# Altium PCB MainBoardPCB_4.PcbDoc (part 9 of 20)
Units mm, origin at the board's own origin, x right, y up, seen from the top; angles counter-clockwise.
Board outline 333.63 x 349.38 mm, 16 copper layers (L1, L2 (GND), L3 (Sign), L4 (GND), L5 (Sign), L6 (PWR/GND), L7(PWR/GND), L8 (Plane_GND), L9 (PWR/GND), L10 (PWR/GND), L11 (PWR/GND), L12 (Sign), L13 (GND), L14 (Sign), L15 (GND), L16), stack 2.502 mm thick; 2205 components, 1648 nets, 8314 pads, 3172 vias.
Unrouted connection lines stored in the file: 5141.
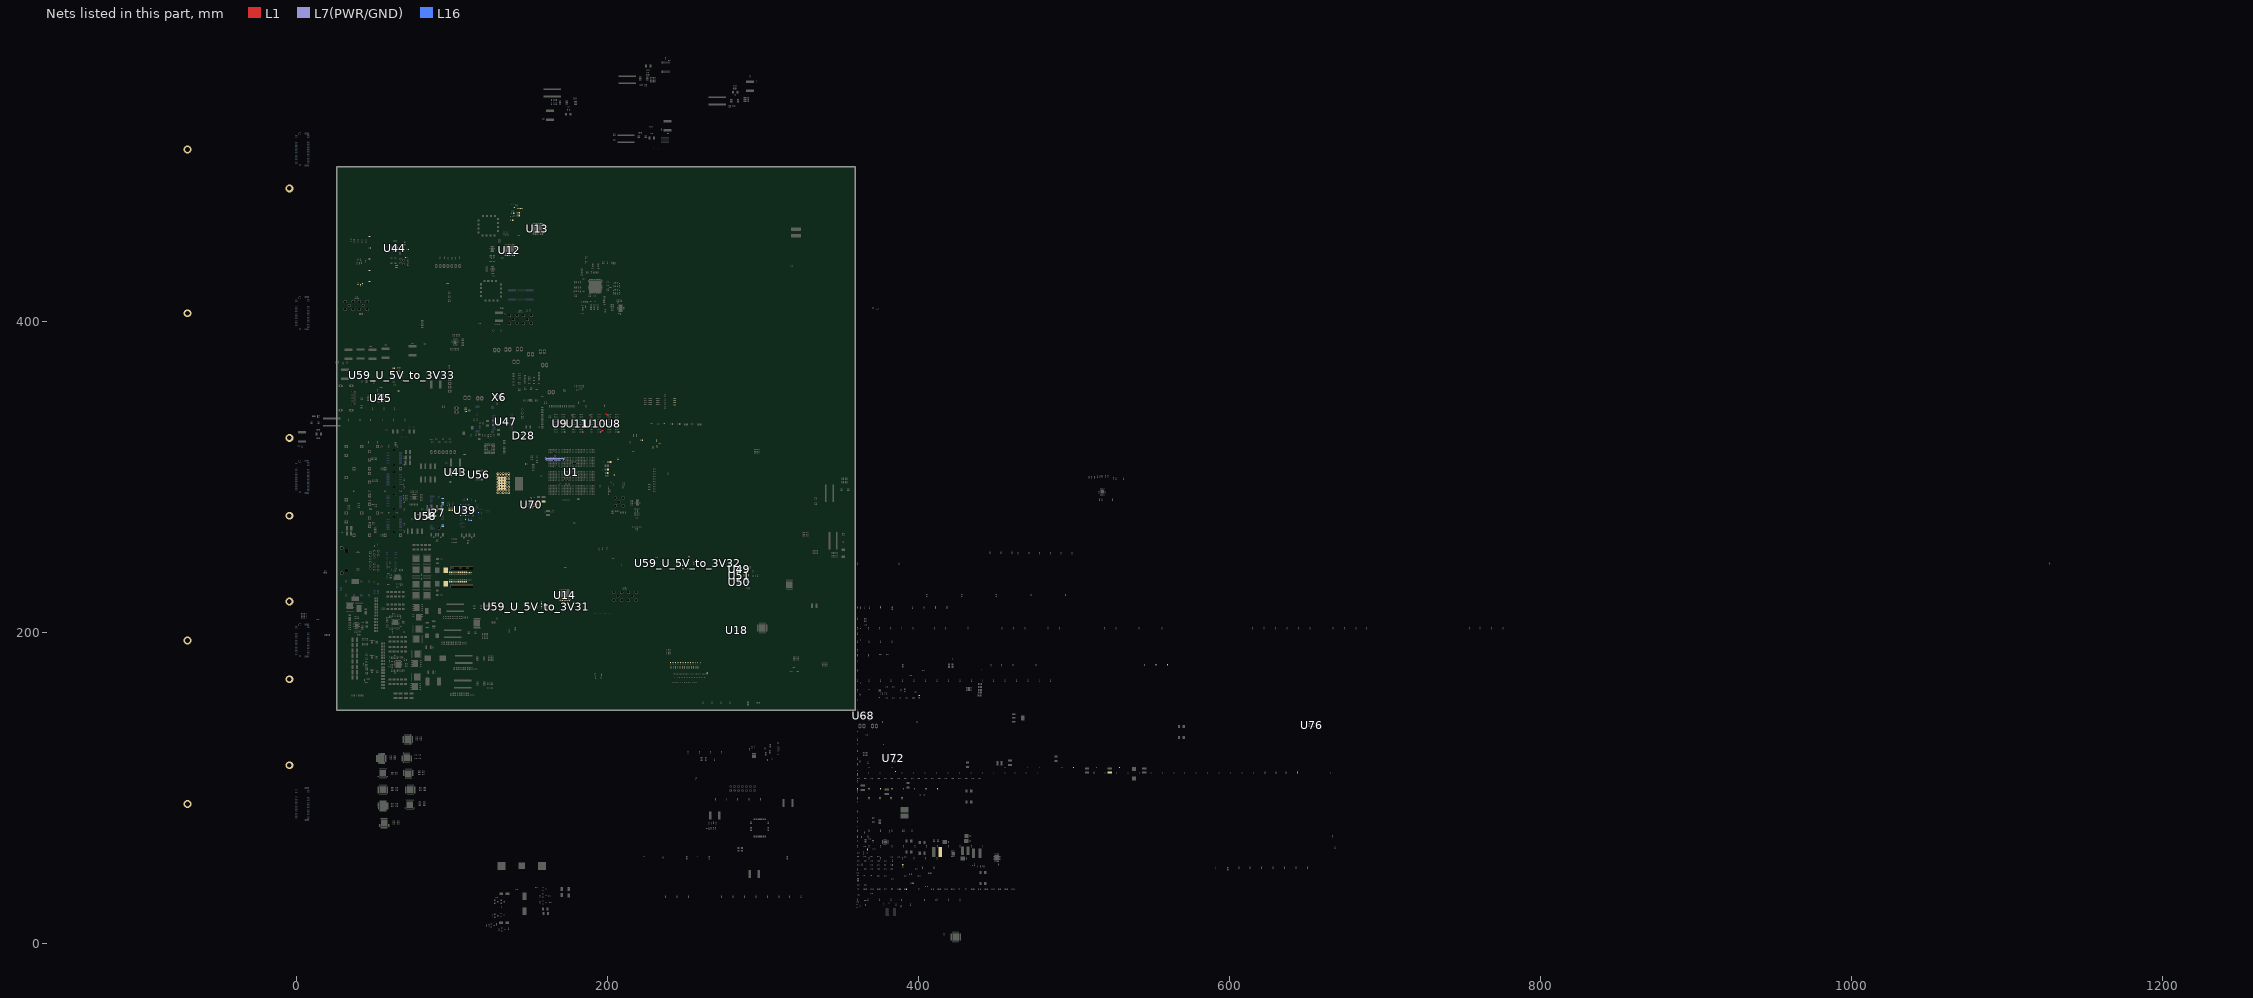
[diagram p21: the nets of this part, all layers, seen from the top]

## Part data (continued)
R532: library part Resistor, "Res Thick Film 0402 75 Ohm 1% 1/10W 100ppm/C Molded SMD SMD Punched Carrier T/R", Case Code (Imperial)=0402, Case Code (Metric)=1005, Manufacturer=Panasonic, Manufacturer Part Number=ERJ-2RKF75R0X, Max Operating Temperature=155°C, Max Power Dissipation=100mW, Min Operating Temperature=-55°C, Package Quantity=1, Supplier Part Number 1=P75.0LDKR-ND, Temperature Coefficient=100ppm/°C, Tolerance=1%, Voltage Rating=50V
R533: library part Resistor, "RES 30 OHM 1% 1/16W 0402", Case/Package=0402, Manufacturer="Stackpole Electronics", Manufacturer Part Number=RMCF0402FT30R0, Max Operating Temperature=155°C, Min Operating Temperature=-55°C, Supplier Part Number 1=RMCF0402FT30R0CT-ND, Temperature Coefficient=100ppm/°C, Tolerance=1%
R536 R537: library part Resistor, "RES SMD 150 OHM 1% 1/10W 0402", Case Code (Imperial)=0402, Case Code (Metric)=1005, Manufacturer=Panasonic, Manufacturer Part Number=ERJ-2RKF1500X, Max Operating Temperature=155°C, Max Power Dissipation=100mW, Min Operating Temperature=-55°C, Package Quantity=1, Supplier Part Number 1=P150LCT-ND, Temperature Coefficient=100ppm/°C, Tolerance=1%, Voltage Rating=50V
R602 R603 R604 R605 R606 R608 R609: library part Resistor, "RES 10K OHM 0.1% 1/16W 0402", Case/Package=0402, Case Code (Metric)=1005, Manufacturer="Stackpole Electronics", Manufacturer Part Number=RNCF0402BTE10K0, Max Operating Temperature=155°C, Max Power Dissipation=63mW, Min Operating Temperature=-55°C, Package Quantity=10000, Supplier Part Number 1=RNCF0402BTE10K0CT-ND, Temperature Coefficient=25ppm/°C, Tolerance=0.1%
R610 R611: library part Resistor, Case/Package=0402, Case Code (Metric)=1005, Manufacturer=Yageo, Manufacturer Part Number=RC0402FR-071K33L, Max Operating Temperature=155°C, Max Power Dissipation=63mW, Min Operating Temperature=-55°C, Package Quantity=1, Power Rating=62.5mW, Supplier Part Number 1=311-1.33KLRCT-ND, Temperature Coefficient=100ppm/°C, Tolerance=1%, Voltage Rating=50V
R612 R614: library part Resistor, Case/Package=0402, Manufacturer="Vishay BCcomponents", Manufacturer Part Number=MCS04020C2203FE000, Max Operating Temperature=125°C, Min Operating Temperature=-55°C, Supplier Part Number 1=749-1566-1-ND, Temperature Coefficient=50ppm/°C, Tolerance=1%
R613 R616: library part Resistor, Case/Package=1206, Case Code (Metric)=3216, Manufacturer="Vishay Dale", Manufacturer Part Number=CRCW12062R40FKEAHP, Max Operating Temperature=155°C, Max Power Dissipation=500mW, Min Operating Temperature=-55°C, Supplier Part Number 1=541-2.40UCT-ND, Temperature Coefficient=100ppm/°C, Tolerance=1%
R617: "RES 0.004 OHM 1% 7W 5931", Case/Package=5931, Manufacturer=Yageo, Max Operating Temperature=170°C, Max Power Dissipation=7W, Min Operating Temperature=-65°C, Resistance=4mR, Supplier Part Number 1=YAG4096CT-ND, Temperature Coefficient=75ppm/°C, Tolerance=1%
R619: library part Resistor, Case/Package=0402, Case Code (Metric)=1005, Manufacturer="Stackpole Electronics", Manufacturer Part Number=RMCF0402FT1K91, Max Operating Temperature=155°C, Max Power Dissipation=63mW, Min Operating Temperature=-55°C, Supplier Part Number 1=RMCF0402FT1K91CT-ND, Temperature Coefficient=100ppm/°C, Tolerance=1%
R620: library part Resistor, Case/Package=0402, Case Code (Metric)=1005, Manufacturer=Yageo, Manufacturer Part Number=RC0402FR-072KL, Max Operating Temperature=155°C, Max Power Dissipation=63mW, Min Operating Temperature=-55°C, Package Quantity=1, Supplier Part Number 1=311-2KLRCT-ND, Temperature Coefficient=100ppm/°C, Tolerance=1%, Voltage Rating=50V
R621: library part Resistor, Case/Package=0402, Case Code (Metric)=1005, Manufacturer="Stackpole Electronics", Manufacturer Part Number=RMCF0402FT147K, Max Operating Temperature=155°C, Max Power Dissipation=63mW, Min Operating Temperature=-55°C, Temperature Coefficient=100ppm/°C, Tolerance=1%
R622: library part Resistor, Case/Package=0402, Case Code (Metric)=1005, Manufacturer="Stackpole Electronics", Manufacturer Part Number=RMCF0402FT340K, Max Operating Temperature=155°C, Max Power Dissipation=63mW, Min Operating Temperature=-55°C, Supplier Part Number 1=RMCF0402FT340KCT-ND, Temperature Coefficient=100ppm/°C, Tolerance=1%
R623: library part Resistor, Case/Package=0402, Case Code (Metric)=1005, Manufacturer=Panasonic, Manufacturer Part Number=ERA-2AEB1431X, Max Operating Temperature=155°C, Max Power Dissipation=63mW, Min Operating Temperature=-55°C, Package Quantity=1, Power Rating=62.5mW, Supplier Part Number 1=P1.43KDCCT-ND, Temperature Coefficient=25ppm/°C, Tolerance=0.1%, Voltage Rating=50V
R624: library part Resistor, Case/Package=0402, Case Code (Metric)=1005, Manufacturer=Panasonic, Manufacturer Part Number=ERJ-2RKF1502X, Max Operating Temperature=155°C, Max Power Dissipation=100mW, Min Operating Temperature=-55°C, Package Quantity=1, Supplier Part Number 1=P15.0KLDKR-ND, Temperature Coefficient=100ppm/°C, Tolerance=1%, Voltage Rating=50V
R625: library part Resistor, "Thick Film Resistors - SMD 1.4K OHM 1%", Case/Package=0402, Case Code (Metric)=1005, Manufacturer=Yageo, Manufacturer Part Number=RC0402FR-071K4L, Max Operating Temperature=155°C, Max Power Dissipation=63mW, Min Operating Temperature=-55°C, Power Rating=62.5mW, Supplier Part Number 1=YAG3039CT-ND, Temperature Coefficient=100ppm/°C, Tolerance=1%, Voltage Rating=50V
R626: library part Resistor, Case/Package=0402, Manufacturer="Vishay BCcomponents", Manufacturer Part Number=MCS04020C2003FE000, Max Operating Temperature=125°C, Min Operating Temperature=-55°C, Supplier Part Number 1=749-1562-1-ND, Temperature Coefficient=50ppm/°C, Tolerance=1%
R627: library part Resistor, Case/Package=0402, Case Code (Metric)=1005, Manufacturer=Yageo, Manufacturer Part Number=RC0402FR-0710K5L, Max Operating Temperature=155°C, Max Power Dissipation=63mW, Min Operating Temperature=-55°C, Power Rating=62.5mW, Supplier Part Number 1=YAG2951CT-ND, Temperature Coefficient=100ppm/°C, Tolerance=1%, Voltage Rating=50V
R628: library part Resistor, Case/Package=0402, Case Code (Metric)=1005, Manufacturer="Stackpole Electronics", Manufacturer Part Number=RMCF0402FT750K, Max Operating Temperature=155°C, Max Power Dissipation=63mW, Min Operating Temperature=-55°C, Supplier Part Number 1=RMCF0402FT750KCT-ND, Temperature Coefficient=100ppm/°C, Tolerance=1%
R631: library part Resistor, Case/Package=0402, Case Code (Metric)=1005, Manufacturer="Stackpole Electronics", Manufacturer Part Number=RMCF0402FT5K90, Max Operating Temperature=155°C, Max Power Dissipation=63mW, Min Operating Temperature=-55°C, Supplier Part Number 1=RMCF0402FT5K90CT-ND, Temperature Coefficient=100ppm/°C, Tolerance=1%
R644: library part Resistor, Case/Package=0402, Case Code (Metric)=1005, Manufacturer=Vishay, Manufacturer Part Number=CRCW04029K10FKED, Max Operating Temperature=155°C, Max Power Dissipation=63mW, Min Operating Temperature=-55°C, Package Quantity=10, Supplier Part Number 1=541-9.10KLCT-ND, Temperature Coefficient=100ppm/°C, Tolerance=1%, Voltage Rating=50V
R645: library part Resistor, Case/Package=0402, Case Code (Metric)=1005, Manufacturer=Panasonic, Manufacturer Part Number=ERA-2AED133X, Max Operating Temperature=155°C, Max Power Dissipation=63mW, Min Operating Temperature=-55°C, Package Quantity=1, Power Rating=62.5mW, Supplier Part Number 1=P13KDECT-ND, Temperature Coefficient=25ppm/°C, Tolerance=0.5%
R647: library part Resistor, "RES SMD 100K OHM 1% 1/16W 0402", Case Code (Imperial)=0402, Case Code (Metric)=1005, Manufacturer=Yageo, Manufacturer Part Number=RC0402FR-07100KL, Max Operating Temperature=155°C, Max Power Dissipation=63mW, Min Operating Temperature=-55°C, Package Quantity=1, Supplier Part Number 1=311-100KLRDKR-ND, Temperature Coefficient=100ppm/°C, Tolerance=1%, Voltage Rating=50V
R648: library part Resistor, "RES SMD 2 OHM 5% 1/16W 0402", Case Code (Imperial)=0402, Case Code (Metric)=1005, Manufacturer=Yageo, Manufacturer Part Number=RC0402JR-072RL, Max Operating Temperature=155°C, Min Operating Temperature=-55°C, Package Quantity=10000, Power Rating=62.5mW, Supplier Part Number 1=311-2.0JRCT-ND, Temperature Coefficient=200ppm/°C, Tolerance=5%, Voltage Rating=50V
R650: library part Resistor, "RES SMD 100M OHM 5% 1/16W 0402", Case Code (Imperial)=0402, Case Code (Metric)=1005, Manufacturer="Stackpole Electronics", Manufacturer Part Number=HMC0402JT100M, Max Operating Temperature=125°C, Max Power Dissipation=63mW, Min Operating Temperature=-55°C, Supplier Part Number 1=HMC0402JT100MCT-ND, Temperature Coefficient=400ppm/°C, Tolerance=5%
R652: library part Resistor, "RES SMD 1M OHM 1% 1/16W 0402", Case Code (Imperial)=0402, Case Code (Metric)=1005, Manufacturer=Yageo, Manufacturer Part Number=RC0402FR-071ML, Max Operating Temperature=155°C, Min Operating Temperature=-55°C, Power Rating=63mW, Supplier Part Number 1=311-1.00MLRDKR-ND, Temperature Coefficient=100ppm/°C, Tolerance=1%, Voltage Rating=50V
R653: library part Resistor, "RES SMD 20 OHM 5% 1/5W 0402", Case Code (Imperial)=0402, Case Code (Metric)=1005, Manufacturer=Rohm, Manufacturer Part Number=ESR01MZPJ200, Max Operating Temperature=155°C, Max Power Dissipation=200mW, Min Operating Temperature=-55°C, Package Quantity=1, Supplier Part Number 1=RHM1011CT-ND, Temperature Coefficient=200ppm/°C, Tolerance=5%
R666: library part Resistor, "RES 0.012 OHM 1% 1/2W 1206", Case/Package=1206, Case Code (Metric)=3216, Manufacturer="Stackpole Electronics", Manufacturer Part Number=CSR1206FK12L0, Max Operating Temperature=155°C, Max Power Dissipation=500mW, Min Operating Temperature=-55°C, Supplier Part Number 1=CSR1206FK12L0CT-ND, Temperature Coefficient=100ppm/°C, Tolerance=1%
R667: library part Resistor, "RES SMD 24.9KOHM 0.1% 1/16W 0402", Case/Package=0402, Case Code (Metric)=1005, Manufacturer=Panasonic, Manufacturer Part Number=ERA-2AEB2492X, Max Operating Temperature=155°C, Max Power Dissipation=63mW, Min Operating Temperature=-55°C, Package Quantity=1, Supplier Part Number 1=P24.9KDCCT-ND, Temperature Coefficient=25ppm/°C, Tolerance=0.1%, Voltage Rating=25V, Voltage Rating (DC)=50V
R668 R676 R745: library part Resistor, "RES SMD 20K OHM 1% 1/16W 0402", Case/Package=0402, Case Code (Metric)=1005, Manufacturer=Vishay, Manufacturer Part Number=CRCW040220K0FKED, Max Operating Temperature=155°C, Max Power Dissipation=63mW, Min Operating Temperature=-55°C, Package Quantity=10, Supplier Part Number 1=51X8496, Temperature Coefficient=100ppm/°C, Tolerance=1%, Voltage Rating=50V
R671 R673: library part Resistor, Case/Package=0402, Case Code (Metric)=1005, Manufacturer=Panasonic, Manufacturer Part Number=ERA-2AEB1871X, Max Operating Temperature=155°C, Max Power Dissipation=63mW, Min Operating Temperature=-55°C, Package Quantity=10000, Power Rating=62.5mW, Supplier Part Number 1=P1.87KDCCT-ND, Temperature Coefficient=25ppm/°C, Tolerance=0.1%
R672: library part Resistor, Case/Package=0402, Case Code (Metric)=1005, Manufacturer=Panasonic, Manufacturer Part Number=ERA-2AEB152X, Max Operating Temperature=155°C, Max Power Dissipation=63mW, Min Operating Temperature=-55°C, Package Quantity=10000, Supplier Part Number 1=P1.5KDCCT-ND, Temperature Coefficient=25ppm/°C, Tolerance=0.1%, Voltage Rating=25V
R674: library part Resistor, Case/Package=0402, Case Code (Metric)=1005, Manufacturer=Panasonic, Manufacturer Part Number=ERA-2AEB153X, Max Operating Temperature=155°C, Max Power Dissipation=63mW, Min Operating Temperature=-55°C, Package Quantity=1, Supplier Part Number 1=P15KDCCT-ND, Temperature Coefficient=25ppm/°C, Tolerance=0.1%, Voltage Rating=25V
R682: library part Resistor, Case/Package=0402, Case Code (Metric)=1005, Manufacturer 1=Yageo, Manufacturer Part Number 1=RC0402FR-077K5L, Max Operating Temperature=155°C, Max Power Dissipation=63mW, Min Operating Temperature=-55°C, Package Quantity=1, Supplier Part Number 1=311-7.50KLRCT-ND, Temperature Coefficient=100ppm/°C, Tolerance=1%, Voltage Rating=50V
R684: library part Resistor, Case/Package=0402, Case Code (Metric)=1005, Manufacturer 1=Yageo, Manufacturer Part Number 1=RC0402FR-077K15L, Max Operating Temperature=155°C, Max Power Dissipation=63mW, Min Operating Temperature=-55°C, Power Rating=62.5mW, Supplier Part Number 1=YAG3235CT-ND, Temperature Coefficient=100ppm/°C, Tolerance=1%, Voltage Rating=50V
R685: library part Resistor, Case/Package=0402, Case Code (Metric)=1005, Manufacturer 1=Yageo, Manufacturer Part Number 1=RC0402FR-075K9L, Max Operating Temperature=155°C, Max Power Dissipation=63mW, Min Operating Temperature=-55°C, Power Rating=62.5mW, Supplier Part Number 1=YAG3197CT-ND, Temperature Coefficient=100ppm/°C, Tolerance=1%, Voltage Rating=50V
R686: library part Resistor, Case/Package=0402, Case Code (Metric)=1005, Manufacturer=Yageo, Manufacturer Part Number=RC0402FR-07412KL, Max Operating Temperature=155°C, Max Power Dissipation=63mW, Min Operating Temperature=-55°C, Power Rating=62.5mW, Supplier Part Number 1=YAG3153CT-ND, Temperature Coefficient=100ppm/°C, Tolerance=1%, Voltage Rating=50V
R687: library part Resistor, Case/Package=0402, Case Code (Metric)=1005, Manufacturer=Panasonic, Manufacturer Part Number=ERA-2AEB5762X, Max Operating Temperature=155°C, Max Power Dissipation=63mW, Min Operating Temperature=-55°C, Package Quantity=1, Power Rating=62.5mW, Supplier Part Number 1=P57.6KDCCT-ND, Temperature Coefficient=25ppm/°C, Tolerance=0.1%, Voltage Rating=50V
R689 R691 R838 R840 R841: library part Resistor, Case/Package=0402, Case Code (Metric)=1005, Manufacturer=Panasonic, Manufacturer Part Number=ERJ-2RKF2002X, Max Operating Temperature=155°C, Max Power Dissipation=100mW, Min Operating Temperature=-55°C, Package Quantity=1, Supplier Part Number 1=P20.0KLCT-ND, Temperature Coefficient=100ppm/°C, Tolerance=1%, Voltage Rating=50V
R695: library part Resistor, Case/Package=0402, Case Code (Metric)=1005, Manufacturer=Panasonic, Manufacturer Part Number=ERA-2AEB101X, Max Operating Temperature=155°C, Max Power Dissipation=63mW, Min Operating Temperature=-55°C, Package Quantity=10000, Supplier Part Number 1=P100DCCT-ND, Temperature Coefficient=25ppm/°C, Tolerance=0.1%, Voltage Rating=25V
R716 R717 R718 R719 R720: library part Resistor, "Thick Film Resistors 0402 261ohms 1% AEC-Q200", Case/Package=0402, Case Code (Metric)=1005, Manufacturer=Panasonic, Manufacturer Part Number=ERJ-2RKF2610X, Max Operating Temperature=155°C, Max Power Dissipation=100mW, Min Operating Temperature=-55°C, Package Quantity=1, Supplier Part Number 1=P261LCT-ND, Temperature Coefficient=100ppm/°C, Tolerance=1%, Voltage Rating=50V
R764: "RES 0.004 OHM 1% 10W 2818", Case/Package=Nonstandard, Manufacturer=Vishay, Max Operating Temperature=170°C, Max Power Dissipation=10W, Min Operating Temperature=-65°C, Resistance=4mR, Supplier Part Number 1=541-3274-1-ND, Temperature Coefficient=200ppm/°C, Tolerance=1%
S1 S5: library part "SW DIP-4"
S2 S3 S4 S6 S7: "WS-TASV SMT Tact Switch 4.5x4.5mm, height 3.8mm, 160gf", Operating Temperature="-40 to +85degC", Rated Current=50mA, Rated Voltage=12VDC
T5 T6 T9 T10 T13 T15 T17 T19: "MOSFET N-CH 30V 53A TDSON-8", Continuous Drain Current (ID)=53A, Drain to Source Breakdown Voltage=30V, Drain to Source Resistance=8mR, Gate to Source Voltage (Vgs)=20V, Input Capacitance=1.7nF, Manufacturer 1=Infineon, Max Operating Temperature=150°C, Max Power Dissipation=35W, Min Operating Temperature=-55°C, Package Quantity=1, Power Dissipation=2.5W, Supplier Part Number 1=BSC080N03LSGATMA1CT-ND, Threshold Voltage=2.2V
T7 T8 T11 T12 T14 T16 T18 T20: "MOSFET, N CH, 100A, 30V, PG-TDSON-8", Case/Package=TO-252-3, Continuous Drain Current (ID)=100A, Drain to Source Breakdown Voltage=30V, Drain to Source Resistance=4.7mR, Gate to Source Voltage (Vgs)=20V, Input Capacitance=4.3nF, Manufacturer 1=Infineon, Max Operating Temperature=150°C, Max Power Dissipation=69W, Min Operating Temperature=-55°C, Package Quantity=5000, Power Dissipation=2.5W, Supplier Part Number 1="BSC030N03LS G-ND", Threshold Voltage=1V
T21: "WE-RJ45 LAN Transformer, THT, 10/100/1000 Base-T, Port 1x1, Tab Up", Operating Temperature="-40 to +85degC"
T22 T23 T27 T30: "MOSFET MOSFT P-Ch -4.3A 50mOhm 10nC Log Lvl", Case/Package=SOT-23, Continuous Drain Current (ID)=4.3A, Current Rating=-4.3A, Drain to Source Breakdown Voltage=-12V, Drain to Source Resistance=50mR, Drain to Source Voltage (Vdss)=12V, Gate to Source Voltage (Vgs)=8V, Input Capacitance=830pF, Manufacturer="International Rectifier", Max Operating Temperature=150°C, Max Power Dissipation=1.3W, Min Operating Temperature=-55°C, Package Quantity=1, Supplier Part Number 1=IRLML6401PBFCT-ND, Threshold Voltage=-550mV
T24 T25 T26 T28 T29 T31 T36: "Trans MOSFET N-CH 8V 6A 3-Pin SOT-23 T/R", Case/Package=SOT-23, Continuous Drain Current (ID)=6A, Drain to Source Voltage (Vdss)=8V, Gate to Source Voltage (Vgs)=5V, Input Capacitance=1.07nF, Manufacturer=Vishay, Max Operating Temperature=150°C, Max Power Dissipation=2.5W, Min Operating Temperature=-55°C, Package Quantity=3000, Power Dissipation=1.3W, Supplier Part Number 1=SI2342DS-T1-GE3CT-ND, Threshold Voltage=800mV
T34: "MOSFET N-CH 60V 25A LFPAK", Continuous Drain Current (ID)=25A, Drain to Source Resistance=14MR, Drain to Source Voltage (Vdss)=60V, Gate to Source Voltage (Vgs)=20V, Input Capacitance=2.03nF, Manufacturer=Renesas, Max Operating Temperature=150°C, Max Power Dissipation=45W, Min Operating Temperature=-55°C, Package Quantity=1, Supplier Part Number 1=968-RJK0651DPB-00#J5
T35: "MOSFET 80V 6.2mOhm@10V 60A N-Ch MV T-FET", Continuous Drain Current (ID)=60A, Drain to Source Breakdown Voltage=80V, Drain to Source Resistance=6.2mR, Gate to Source Voltage (Vgs)=20V, Input Capacitance=2.425nF, Manufacturer=Vishay, Max Operating Temperature=150°C, Max Power Dissipation=69.4W, Min Operating Temperature=-55°C, On-State Resistance=9.5MR, Package Quantity=1, Supplier Part Number 1=SIJ482DP-T1-GE3CT-ND, Threshold Voltage=1.5V
TP1_I2C_Bridge TP1_I2C_Bridge_2 TP1_I2C_Bridge_3 TP2_I2C_Bridge TP2_I2C_Bridge_2 TP2_I2C_Bridge_3 TP3_I2C_Bridge TP3_I2C_Bridge_2 TP3_I2C_Bridge_3 TP4_I2C_Bridge TP4_I2C_Bridge_2 TP4_I2C_Bridge_3 TP5_I2C_Bridge TP5_I2C_Bridge_2 TP5_I2C_Bridge_3 TP6_I2C_Bridge TP6_I2C_Bridge_2 TP6_I2C_Bridge_3 TP7_I2C_Bridge_2 TP8_I2C_Bridge TP8_I2C_Bridge_2 TP8_I2C_Bridge_3 TP9_I2C_Bridge TP9_I2C_Bridge_2 TP9_I2C_Bridge_3 TP10_I2C_Bridge TP10_I2C_Bridge_2 TP10_I2C_Bridge_3 TP11_I2C_Bridge TP11_I2C_Bridge_2 TP11_I2C_Bridge_3 TP12_I2C_Bridge_2 TP13_I2C_Bridge_2 TP14_I2C_Bridge_2 TP15_I2C_Bridge TP15_I2C_Bridge_2 TP15_I2C_Bridge_3 TP16_I2C_Bridge TP16_I2C_Bridge_2 TP16_I2C_Bridge_3 TP17_I2C_Bridge TP17_I2C_Bridge_2 TP17_I2C_Bridge_3 TP18_I2C_Bridge TP18_I2C_Bridge_2 TP18_I2C_Bridge_3 TP19 TP20 TP33 TP34 TP35 TP36 TP37 TP38 TP39 TP40 TP41 TP42 TP43 TP44 TP45 TP46 TP47 TP48 TP49 TP50_SPI_bridge2 TP50_SPI_bridge3 TP51_SPI_bridge2 TP51_SPI_bridge3 TP52_SPI_bridge2 TP52_SPI_bridge3 TP53_SPI_bridge1 TP53_SPI_bridge2 TP53_SPI_bridge3 TP54_SPI_bridge2 TP55_SPI_bridge2 TP56_SPI_bridge1 TP56_SPI_bridge2 TP56_SPI_bridge3 TP57_SPI_bridge1 TP57_SPI_bridge2 TP57_SPI_bridge3 TP58_SPI_bridge1 TP58_SPI_bridge2 TP58_SPI_bridge3 TP59_SPI_bridge1 TP59_SPI_bridge2 TP59_SPI_bridge3 TP60_U_Translator_I2C1 TP60_U_Translator_I2C2 TP60_U_Translator_I2C3 TP60_U_Translator_I2C4 TP61_U_Translator_I2C1 TP61_U_Translator_I2C2 TP61_U_Translator_I2C3 TP61_U_Translator_I2C4 TP62 TP63 TP64 TP65 TP66 TP67 TP68 TP69 TP70 TP71 TP72 TP73 TP74 TP75 TP76 TP77 TP78 TP79 TP80 TP81 TP82 TP83 TP84 TP85 TP86 TP87 TP88 TP91 TP92: "TEstPoint", Color=Black, Flammability Rating="UL94 V-0", Manufacturer="Keystone Electronics", Manufacturer Part Number=5001, Package Quantity=100, Supplier Part Number 1=36-5001-ND
U1: "FPGA Zynq UltraScale+ Family 192150 Cells 20nm Technology 0.85V 900-Pin FCBGA Tray", Case/Package=FCBGA, Frequency=500MHz, Manufacturer=Xilinx, Manufacturer Part Number=XCZU4CG-1FBVB900E, Max Operating Temperature=100°C, Min Operating Temperature=0°C, Supplier Part Number 1=217-CZU4CG-1FBVB900E
U3_I2C_Bridge U3_I2C_Bridge_2 U3_I2C_Bridge_3: "8X I2C Switch", Case/Package=VQFN, Manufacturer="Texas Instruments", Manufacturer Part Number=TCA9548ARGER, Max Operating Temperature=85°C, Max Supply Current=80uA, Max Supply Voltage=5.5V, Min Operating Temperature=-40°C, Min Supply Voltage=1.65V, On-State Resistance=70R, Package Quantity=3000, Supplier Part Number 1=296-39222-1-ND
U4 U5 U48: Manufacturer 1="Texas Instruments", Supplier Part Number 1=296-53412-1-ND
U6 U7 U17 U18 U20 U21 U22 U23 U46: "Current Limit Load Switch with OVP and TRCB, 28 V, 5 A", Manufacturer 1="ON Semiconductor", Supplier Part Number 1=863-FPF2895CUCX
U8 U9 U10 U11: "RAM 8GB", Frequency=1.2GHz, Manufacturer="Micron Technology", Manufacturer Part Number=MT40A512M16JY-083EIT:BTR, Max Operating Temperature=95°C, Min Operating Temperature=-40°C, Supplier Part Number 1=557-1690-2-ND
U12 U13 U14: "Dystrybutor Zegarów", Manufacturer="Analog Devices", Manufacturer Part Number=LTC6952IUKG#PBF, Supplier Part Number 1=LTC6952IUKG#PBF-ND
U15 U24_SPI_bridge1 U24_SPI_bridge2 U24_SPI_bridge3 U25_SPI_bridge1 U25_SPI_bridge2 U25_SPI_bridge3 U26_SPI_bridge1 U26_SPI_bridge2 U26_SPI_bridge3 U27_SPI_bridge1 U27_SPI_bridge2 U27_SPI_bridge3 U28_SPI_bridge1 U28_SPI_bridge2 U28_SPI_bridge3 U43 U53 U56 U57 U79: Manufacturer 1="Texas Instruments", Supplier Part Number 1=296-SN74AXC4T774PWRCT-ND
U16: Manufacturer="Texas Instruments", Manufacturer Part Number=LMK05028RGCR, Supplier Part Number 1=296-49099-1-ND
U19: "Quad 40 V / 1 A Step-Down Switching Regulator with 100% Duty Cycle Operation, 28-pin QFN (UFD-28), -40 to 125 degC, Pb-Free", Manufacturer="Linear Technology", Supplier Part Number 1=LT3504EUFD#PBF-ND
U30: "DAC 20bit", Case/Package=SSOP, Manufacturer="Texas Instruments", Manufacturer Part Number=DAC1220E, Max Operating Temperature=85°C, Max Supply Voltage=5.25V, Min Operating Temperature=-40°C, Min Supply Voltage=4.75V, Nominal Supply Current=460uA, Operating Supply Voltage=5V, Package Quantity=75, Power Consumption=2.5mW, Supplier Part Number 1=DAC1220E-ND
U31 U32: "IC BUFFER 2:4 LVPECL MUX 16QFN", Case/Package=QFN, Frequency=1.25GHz, Manufacturer 1="Silicon Labs", Max Operating Temperature=85°C, Max Supply Voltage=3.63V, Min Operating Temperature=-40°C, Min Supply Voltage=2.38V, Nominal Supply Current=210mA, Package Quantity=100, Supplier Part Number 1=336-2500-5-ND
U33: "IC, BUF LVPECL CLOCK DRVR 16-VQFN", Case/Package=QFN, Frequency=800MHz, Input Current=10uA, Manufacturer="Texas Instruments", Max Operating Temperature=85°C, Max Supply Voltage=3.6V, Min Operating Temperature=-40°C, Min Supply Voltage=3V, Package Quantity=1, Supplier Part Number 1=296-17045-1-ND
U34 U37 U38: "Analog Devices", Case/Package="LFCSP EP", Max Input Voltage=20V, Max Operating Temperature=85°C, Max Output Current=30A, Min Input Voltage=2.75V, Min Operating Temperature=-40°C, Nominal Supply Current=4.5mA, Operating Supply Current=100uA, Output Current=25A, Output Voltage=18V, Supplier Part Number 1=ADP1850ACPZ-R7CT-ND, Switching Frequency=1.5MHz
U35_I2C_Expander1 U35_I2C_Expander1_1 U35_I2C_Expander2 U35_I2C_Expander2_1 U35_I2C_Expander3 U35_I2C_Expander3_1 U35_I2C_Expander? U35_I2C_Expander_10 U35_I2C_Expander_11 U35_I2C_Expander_12 U35_I2C_Expander_13 U35_I2C_Expander_14 U35_I2C_Expander_16 U35_I2C_Expander_16_1: "16-Bit I/O Expander with Serial Interface, 28-Pin QFN, Extended Temperature", Manufacturer=Microchip, Supplier Part Number 1=MCP23017-E/ML-ND
U36_U_Translator_I2C1 U36_U_Translator_I2C2 U36_U_Translator_I2C3 U36_U_Translator_I2C4: "I2C [V] Level translator", Low Level Output Current=128mA, Manufacturer="Texas Instruments", Manufacturer Part Number=PCA9306DQER, Max Operating Temperature=85°C, Max Supply Voltage=5V, Min Operating Temperature=-40°C, Min Supply Voltage=0uV, Package Quantity=1, Supplier Part Number 1=296-27957-1-ND
U39: "IC ETHERNET PHY 48VQFN", Case/Package=VQFN, Manufacturer 1="Texas Instruments", Max Operating Temperature=105°C, Max Supply Voltage=2.625V, Min Operating Temperature=-40°C, Min Supply Voltage=950mV, Supplier Part Number 1=296-43254-1-ND
U40 U42 U49 U50 U51 U59_5V_to_3V3_for_FTDI U59_U_5V_to_3V31 U59_U_5V_to_3V32 U59_U_5V_to_3V33: "IC REG LDO ADJ 1.5A 8DFN", Case/Package=DFN, Dropout Voltage=330mV, Input Bias Current=120uA, Manufacturer 1=Microchip, Max Input Voltage=6V, Max Operating Temperature=125°C, Max Output Current=1.5A, Min Input Voltage=2.3V, Min Operating Temperature=-40°C, Output Voltage=5V, Package Quantity=3300, Reference Voltage=410mV, Supplier Part Number 1=MCP1727T-ADJE/MFCT-ND
U41: "IC FLASH 64G MMC", Manufacturer 1="Micron Technology", Supplier Part Number 1=340-296563-REEL
U44: "IC SUPERVISORY CIRC DL 16TQFN", Manufacturer=Maxim, Max Operating Temperature=125°C, Max Power Dissipation=2W, Max Supply Voltage=28V, Min Operating Temperature=-40°C, Min Supply Voltage=2.2V, Number of Voltages Monitored=2, Operating Supply Current=52uA, Package Quantity=2500, Supplier Part Number 1=MAX16025TE+TCT-ND
U45: "IC TXRX USB 2.0 FLEXPWR 32QFN", Case/Package=QFN, Frequency=60MHz, Manufacturer 1=Microchip, Max Operating Temperature=85°C, Min Operating Temperature=-40°C, Operating Supply Current=18uA, Operating Supply Voltage=5.5V, Package Quantity=4000, Supplier Part Number 1=USB3320C-EZK-DKR-ND
U47: "Memory Card Interface 25-WLCSP (2.04x2.04)", Manufacturer 1="Nexperia USA", Supplier Part Number 1=1727-8607-1-ND
U54: "MICROCHIP - 93LC56BT-I/OT. - 2K, 128 X 16, SERIAL EE, IND ROHS COMPLIANT: YES", Case/Package=SOT-23, Frequency=2MHz, Manufacturer=Microchip, Max Operating Temperature=85°C, Max Supply Voltage=5.5V, Min Operating Temperature=-40°C, Min Supply Voltage=2.5V, Nominal Supply Current=2mA, Package Quantity=3000, Supplier Part Number 1=93LC56BT-I/OTCT-ND
U55: "IC USB HS QUAD UART/SYNC 64-LQFP", Case/Package=LQFP, Dual Supply Voltage=3.3V, Manufacturer 1=FTDI, Max Operating Temperature=85°C, Max Supply Voltage=3.63V, Min Operating Temperature=-40°C, Min Supply Voltage=1.62V, Operating Supply Current=70mA, Package Quantity=1000, Supplier Part Number 1=768-1026-1-ND
U58: Manufacturer 1=STMicroelectronics, Supplier Part Number 1=497-19784-1-ND
U60 U69: "IC REG LIN POS ADJ 2A 16LFCSP", Case/Package="LFCSP EP", Dropout Voltage=160mV, Manufacturer="Analog Devices", Max Input Voltage=3.6V, Max Operating Temperature=125°C, Max Output Current=2A, Max Output Voltage=3V, Max Supply Current=1.8mA, Min Current Limit=2.4A, Min Input Voltage=1.6V, Min Operating Temperature=-40°C, Min Output Voltage=750mV, Output Voltage Accuracy=1%, Power Supply Rejection Ratio (PSRR)=70dB, Supplier Part Number 1=ADP1741ACPZ-R7CT-ND
U61 U70: "IC REG LINEAR POS ADJ 1A 20QFN", Case/Package=QFN, Dropout Voltage=130mV, Manufacturer="Texas Instruments", Max Operating Temperature=125°C, Min Current Limit=1.5A, Min Operating Temperature=-40°C, Output Current=1A, Output Voltage=5V, Quiescent Current=2mA, Supplier Part Number 1=296-43312-1-ND
U62: "LINEAR TECHNOLOGY         LT3042EDD#PBF             LDO Voltage Regulator, Adjustable, 1.8V to 20V in, 350mV drop, 0V to 15V/0.2A out, DFN-10", Case/Package=DFN, Dropout Voltage=350mV, Manufacturer="Analog Devices / Linear Technology", Max Input Voltage=20V, Max Operating Temperature=125°C, Max Output Voltage=15V, Min Current Limit=220mA, Min Input Voltage=1.8V, Min Operating Temperature=-40°C, Min Output Voltage=0uV, Output Current=200mA, Supplier Part Number 1=LT3042EDD#PBF-ND
U63: "IC TXRX CAN 1MBPS SOT23-8", Case/Package=SOT-23-8, Manufacturer=Maxim, Max Operating Temperature=85°C, Max Supply Current=70mA, Max Supply Voltage=3.465V, Min Operating Temperature=-40°C, Min Supply Voltage=3.135V, Operating Supply Current=35mA, Operating Supply Voltage=3.3V, Package Quantity=1, Supplier Part Number 1=MAX3051EKA+TCT-ND
U64_U_Pomiar_pradu_napiecia_1 U64_U_Pomiar_pradu_napiecia_2 U64_U_Pomiar_pradu_napiecia_3 U64_U_Pomiar_pradu_napiecia_4 U64_U_Pomiar_pradu_napiecia_5 U64_U_Pomiar_pradu_napiecia_6 U64_U_Pomiar_pradu_napiecia_7 U64_U_Pomiar_pradu_napiecia_8 U64_U_Pomiar_pradu_napiecia_9 U64_U_Pomiar_pradu_napiecia_10 U64_U_Pomiar_pradu_napiecia_11 U72: "IC MONITOR PWR/CURR BIDIR 10MSOP", Case/Package=VSSOP, Input Bias Current=10uA, Input Offset Voltage (Vos)=2.5uV, Manufacturer="Texas Instruments", Max Operating Temperature=125°C, Max Supply Voltage=5.5V, Min Operating Temperature=-40°C, Min Supply Voltage=2.7V, Nominal Supply Current=330uA, Output Current=10mA, Package Quantity=1, Supplier Part Number 1=296-29034-1-ND
U65: "IC REG CTRLR BUCK 20-TQFN", Manufacturer=Maxim, Supplier Part Number 1=MAX17557ATP+-ND
U67 U68: "IC PWR SUPPLY SEQUENCER SOT23-6", Case/Package=SOT-23-6, Manufacturer="TI National Semiconductor", Max Operating Temperature=125°C, Max Supply Voltage=5.5V, Min Operating Temperature=-40°C, Min Supply Voltage=2.7V, Number of Voltages Monitored=3, Operating Supply Current=25uA, Overvoltage Threshold=1.4V, Package Quantity=250, Supplier Part Number 1=LM3880MFE-1AF/NOPBCT-ND, Undervoltage Threshold=1V
U71: "IC REG LINEAR 8V 500MA SOT223-4", Case/Package=SOT-223-4, Dropout Voltage=2V, Manufacturer="Texas Instruments", Max Input Voltage=25V, Max Operating Temperature=125°C, Max Output Current=500mA, Min Input Voltage=10.5V, Min Operating Temperature=-40°C, Nominal Output Voltage=8V, Package Quantity=1, Power Supply Rejection Ratio (PSRR)=80dB, Quiescent Current=4.6mA, Supplier Part Number 1=296-12612-1-ND
U73: "IC REG LINEAR POS ADJ 800MA 8DFN", Case/Package=DFN, Dropout Voltage=700mV, Input Bias Current=150uA, Manufacturer=STMicroelectronics, Max Input Voltage=5.5V, Max Operating Temperature=125°C, Max Output Current=800mA, Min Input Voltage=1V, Min Operating Temperature=-40°C, Operating Supply Current=200nA, Output Voltage=4V, Package Quantity=2500, Power Supply Rejection Ratio (PSRR)=80dB, Supplier Part Number 1=497-15098-1-ND, Tolerance=2%
U74 U76: "IC GATE AND 1CH 2-INP SOT23-5", Case/Package=SOT-23, High Level Output Current=-32mA, Low Level Output Current=32mA, Manufacturer="Texas Instruments", Max Operating Temperature=125°C, Max Supply Voltage=5.5V, Min Operating Temperature=-40°C, Min Supply Voltage=1.65V, Package Quantity=1, Quiescent Current=10uA, Supplier Part Number 1=296-11601-1-ND
U75: "TVS DIODE 26.5VWM 44VC SOT323", Case/Package=SOT-323-3, Clamping Voltage=44V, Manufacturer=STMicroelectronics, Max Operating Temperature=175°C, Min Breakdown Voltage=28.5V, Min Operating Temperature=-55°C, Peak Pulse Current=3A, Peak Pulse Power=250W, Power Line Protection=No, Reverse Standoff Voltage=26.5V, Supplier Part Number 1=497-15845-1-ND
U77 U78: "Buffer/Driver 2-CH Non-Inverting Open Drain CMOS 6-Pin MicroPak T/R", Low Level Output Current=32mA, Manufacturer="ON Semiconductor / Fairchild", Max Operating Temperature=85°C, Max Supply Voltage=5.5V, Min Operating Temperature=-40°C, Min Supply Voltage=1.65V, Package Quantity=5000, Quiescent Current=1uA, Supplier Part Number 1=NC7WZ07FHXCT-ND
X1: library part CVCO55CC-2000-2000, Frequency=2GHz, Load Capacitance=22pF, Manufacturer=Crystek, Max Operating Temperature=85°C, Min Operating Temperature=-30°C, Operating Supply Voltage=8V, Package Quantity=1, Supplier Part Number 1=549-CVCO55CC20002000
X2: library part CVCO55CL-0490-0540, Case/Package=SMD/SMT, Frequency=540MHz, Load Capacitance=100pF, Manufacturer=Crystek, Max Operating Temperature=85°C, Max Supply Voltage=5.25V, Min Operating Temperature=-40°C, Min Supply Voltage=4.75V, Package Quantity=5, Supplier Part Number 1=744-1174-ND
X3: library part MP024S, "CRYSTAL 2.4576MHZ 32PF T/H", ESR (Equivalent Series Resistance)=300R, Frequency Stability=50ppm, Frequency Tolerance=30ppm, Load Capacitance=32pF, Manufacturer=CTS, Max Operating Temperature=70°C, Min Operating Temperature=-20°C, Package Quantity=100, Supplier Part Number 1=CTX069-ND
X4: "CRYSTAL 25.0000MHZ 18PF SMD", Case/Package=SMD/SMT, ESR (Equivalent Series Resistance)=50R, Frequency=25MHz, Frequency Stability=30ppm, Frequency Tolerance=50ppm, Load Capacitance=18pF, Manufacturer 1=Epson, Max Operating Temperature=70°C, Min Operating Temperature=-20°C, Package Quantity=250, Supplier Part Number 1=SER3691CT-ND
X5: library part FC-13532.7680KA-A5, "CRYSTAL 32.7680 KHZ 12.5PF SMD", Case/Package=SMD/SMT, ESR (Equivalent Series Resistance)=70kR, Frequency Tolerance=20ppm, Load Capacitance=12.5pF, Manufacturer=Epson, Max Operating Temperature=85°C, Min Operating Temperature=-40°C, Supplier Part Number 1=SER4103CT-ND
X6: "SMD Crystal Oscillator 50MHz 3.3V 4-Pin SMD Tray", Case/Package=SMD/SMT, Frequency=50MHz, Frequency Stability=20ppm, Manufacturer="Silicon Labs", Operating Supply Voltage=3.3V, Package Quantity=1, Supplier Part Number 1=336-5245-ND
X7: "CRYSTAL 24.00 MHZ 9.0PF SMD", Case/Package=SMD/SMT, ESR (Equivalent Series Resistance)=40R, Frequency=24MHz, Frequency Stability=15ppm, Frequency Tolerance=10ppm, Load Capacitance=9pF, Manufacturer 1=Epson, Max Operating Temperature=85°C, Min Operating Temperature=-40°C, Supplier Part Number 1=SER4180DKR-ND
X8: Manufacturer 1="ECS International", Supplier Part Number 1=XC2904CT-ND
X9: "OSC MEMS 48.0000MHZ LVCMOS SMD", Case/Package=SMD/SMT, Frequency=48MHz, Frequency Stability=25ppm, Manufacturer=SiTime, Max Operating Temperature=85°C, Max Supply Current=4.5mA, Min Operating Temperature=-40°C, Supplier Part Number 1=1473-30890-1-ND

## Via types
v1: diameter 0.5, hole 0.2, L1 to L16, tented both sides, 1153 vias
v2: diameter 0.5/0.35/0.35/0.35/0.35/0.35/0.35/0.35/0.35/0.35/0.35/0.35/0.35/0.35/0.35/0.5 (per signal layer), hole 0.2, L1 to L16, tented both sides, 548 vias
v3: diameter 0.5, hole 0.2, L1 to L16, 522 vias
v4: diameter 0.5/0.35/0.35/0.35/0.35/0.35/0.35/0.35/0.35/0.35/0.35/0.35/0.35/0.35/0.35/0.5 (per signal layer), hole 0.15, L1 to L16, tented both sides, 266 vias
v5: diameter 0.8, hole 0.4, L1 to L16, tented both sides, 164 vias
v6: diameter 0.35/0/0.35 (per signal layer), hole 0.127, L1 to L3 (Sign), tented both sides, 132 vias
v7: diameter 2.54, hole 1.02, L1 to L16, 125 vias
v8: diameter 1.4, hole 0.5, L1 to L16, tented both sides, 80 vias
v9: diameter 0.35, hole 0.127, L1 to L2 (GND), tented both sides, 36 vias
v10: diameter 0.4, hole 0.2, L1 to L16, 16 vias
v11: diameter 0.25, hole 0.2, L1 to L16, 16 vias
v12: diameter 5, hole 3, L1 to L16, 15 vias
v13: diameter 0.3, hole 0.2, L1 to L16, 15 vias
v14: diameter 0.45, hole 0.15, L1 to L16, 12 vias
v15: diameter 0.5/0.35/0.35/0.35/0.35/0.35/0.35/0.35/0.35/0.35/0.35/0.35/0.35/0.35/0.35/0.45 (per signal layer), hole 0.15, L1 to L16, tented both sides, 10 vias
v16: diameter 0.2/0/0.2 (per signal layer), hole 0.1, L1 to L3 (Sign), tented both sides, 9 vias
v17: diameter 0.4, hole 0.1, L1 to L16, 7 vias
v18: diameter 0.5, hole 0.2, L3 (Sign) to L6 (PWR/GND), tented both sides, 6 vias
v19: diameter 1.65, hole 1.65, L1 to L16, 6 vias
v20: diameter 1.15, hole 1.15, L1 to L16, 6 vias
v21: diameter 0.35/0/0.35 (per signal layer), hole 0.127, L14 (Sign) to L16, tented both sides, 5 vias
v22: diameter 0.2, hole 0.1, L1 to L16, 4 vias
v23: diameter 0.4, hole 0.2, L1 to L16, tented both sides, 2 vias
v24: diameter 0.4, hole 0.15, L1 to L16, 2 vias
v25: diameter 0.508, hole 0.127, L1 to L2 (GND), 2 vias
v26: diameter 0.508, hole 0.127, L2 (GND) to L3 (Sign), 2 vias
v27: diameter 0.5/0.35/0.35/0.35/0.35/0.35/0.35/0.35/0.35/0.35/0.35/0.35/0.35/0.35/0.35/0.5 (per signal layer), hole 0.15, L1 to L16, 2 vias
v28: diameter 0.35, hole 0.127, L3 (Sign) to L6 (PWR/GND), tented both sides, 2 vias
v29: diameter 5.5, hole 3.5, L1 to L16, 1 vias
v30: diameter 0.5/0.35/0.35/0.35/0.35/0.35/0.35/0.35/0.35/0.35/0.35/0.35/0.35/0.35/0.35/0.5 (per signal layer), hole 0.2, L1 to L16, 1 vias
v31: diameter 0.35/0.35/0.35 (per signal layer), hole 0.127, L1 to L3 (Sign), tented both sides, 1 vias
v32: diameter 0.45/0/0.45 (per signal layer), hole 0.15, L1 to L3 (Sign), tented both sides, 1 vias
v33: diameter 0.45/0/0.45 (per signal layer), hole 0.2, L14 (Sign) to L16, tented both sides, 1 vias
v34: diameter 0.35, hole 0.127, L2 (GND) to L3 (Sign), 1 vias
v35: diameter 0.35, hole 0.127, L1 to L2 (GND), 1 vias

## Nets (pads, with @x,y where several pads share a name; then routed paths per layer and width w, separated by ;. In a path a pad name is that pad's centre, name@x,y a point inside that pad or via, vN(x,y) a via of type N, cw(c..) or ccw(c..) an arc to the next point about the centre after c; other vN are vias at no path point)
0.85V@40A_INA: C359.2 C360.2 C361.2 C362.2 C363.2 C364.2 C365.2 C366.2 C367.2 C368.2 C369.2 C370.2 C377.2 C378.2 C379.2 C380.2 C381.2 C382.2 C383.2 C384.2 C385.2 C386.2 C387.2 C388.2 L9.2 L10.2 R617.1 U72.10 | length 0.2
  L7(PWR/GND) w0.3: 116.278,181.956 116.278,182.159
  other v1: 99.543,228.727 100.232,228.727 100.922,228.727 101.612,228.727 102.302,228.727 102.991,228.727 103.681,228.727 104.371,228.727 105.061,228.727 105.75,228.727 106.44,228.727 107.13,228.727 107.82,228.727 108.509,228.727 109.199,228.727 109.889,228.727 110.579,228.727 111.268,228.727 111.958,228.727 112.648,228.727 113.338,228.727 99.554,229.517 100.244,229.517 100.933,229.517 101.623,229.517 102.313,229.517 103.003,229.517 103.693,229.517 104.382,229.517 105.072,229.517 105.762,229.517 106.452,229.517 107.141,229.517 107.831,229.517 108.521,229.517 109.211,229.517 109.9,229.517 110.59,229.517 111.28,229.517 111.97,229.517 112.659,229.517 113.349,229.517 99.554,230.34 100.244,230.34 100.933,230.34 101.623,230.34 102.313,230.34 103.003,230.34 103.693,230.34 104.382,230.34 105.072,230.34 105.762,230.34 106.452,230.34 107.141,230.34 107.831,230.34 108.521,230.34 109.211,230.34 109.9,230.34 110.59,230.34 111.28,230.34 111.97,230.34 112.659,230.34 113.349,230.34 99.543,240.424 100.232,240.424 100.922,240.424 101.612,240.424 102.302,240.424 102.991,240.424 103.681,240.424 104.371,240.424 105.061,240.424 105.75,240.424 106.44,240.424 107.13,240.424 107.82,240.424 108.509,240.424 109.199,240.424 109.889,240.424 110.579,240.424 111.268,240.424 111.958,240.424 112.648,240.424 113.338,240.424 99.554,241.214 100.244,241.214 100.933,241.214 101.623,241.214 102.313,241.214 103.003,241.214 103.693,241.214 104.382,241.214 105.072,241.214 105.762,241.214 106.452,241.214 107.141,241.214 107.831,241.214 108.521,241.214 109.211,241.214 109.9,241.214 110.59,241.214 111.28,241.214 111.97,241.214 112.659,241.214 113.349,241.214 99.554,242.037 100.244,242.037 100.933,242.037 101.623,242.037 102.313,242.037 103.003,242.037 103.693,242.037 104.382,242.037 105.072,242.037 105.762,242.037 106.452,242.037 107.141,242.037 107.831,242.037 108.521,242.037 109.211,242.037 109.9,242.037 110.59,242.037 111.28,242.037 111.97,242.037 112.659,242.037 113.349,242.037
  other v8: 129.565,289.776 131.318,289.776 133.071,289.776 134.823,289.776 136.576,289.776 129.565,291.529 131.318,291.529 133.071,291.529 134.823,291.529 136.576,291.529 129.565,293.282 131.318,293.282 133.071,293.282 134.823,293.282 136.576,293.282 129.565,295.034 131.318,295.034 133.071,295.034 134.823,295.034 136.576,295.034 129.565,296.787 131.318,296.787 133.071,296.787 134.823,296.787 136.576,296.787 129.565,298.539 131.318,298.539 133.071,298.539 134.823,298.539 136.576,298.539 129.565,300.292 131.318,300.292 133.071,300.292 134.823,300.292 136.576,300.292 129.565,302.045 131.318,302.045 133.071,302.045 134.823,302.045 136.576,302.045
  other v12: -69.975,89.581 -4.475,114.582 -4.475,169.813 -69.975,194.813 -4.475,219.813 -4.475,275.045 -4.475,325.045 -69.975,405.276 -4.475,485.508 -69.975,510.508
  other v19: 2.275,204.813 91.921,267.021 2.275,310.045 2.275,415.276 2.275,520.508
  other v20: 2.275,184.813 91.921,287.021 2.275,290.045 2.275,395.276 2.275,500.508
0V9@1A_REG3: C709.2 C710.2 R673.2 U1.A10 U1.C10 U1.F8 U1.H8 U1.M8 U1.P8 U70.11 U70.12 | length 2.8
  L1 w0.3: U70.11@152.889,281.004 v5(153.784,281.004) v5@153.797,281.004 ; U70.12@152.889,281.504 v5(154.745,281.503)
  other v2: 167.397,295.539 169.397,295.539 173.397,295.539 175.397,295.539 162.397,297.539 164.397,297.539
  other v5: 151.752,286.093 150.812,286.74 152.781,286.779
0V85@2A: C675.2 C746.2 FB45.2 U1.J23 U1.L23 | length 24.2
  L7(PWR/GND) w0.254: 160.122,311.721 160.769,311.074 169.862,311.074 v2(170.397,310.539) ; 160.223,312.509 160.706,312.026 171.59,312.026 171.907,311.709 171.907,311.029 v2(172.397,310.539)
1V0@1.5A: C505.2 C506.2 C507.2 C508.2 C509.2 C510.2 C511.2 C512.2 C513.2 C514.2 C555.2 R397.2 U39.6 U39.24 U39.31 U39.42 U51.8
1V8@0.5A_ADC_filtered: C705.2 C706.2 C749.2 C750.2 C757.1 C758.2 D28.3 FB38.1 FB40.1 FB42.1 R671.2 R694.1 R745.2 U1.K10 U1.L10 U1.M10 U1.N10 U1.P10 U1.T22 U1.U21 U1.V21 U1.V22 U70.14 U70.15 | length 3.6
  L1 w0.254: C706.2@181.152,285.703 v2(182.038,285.703)
  L1 w0.3: U70.14@152.889,282.504 v5(154.745,282.504) ; U70.15@152.889,283.003 v5(153.784,283.003) v5@153.797,283.003
  other v2: 171.397,297.539 172.397,297.539 173.397,297.539 174.397,297.539 175.397,297.539 178.397,308.539 179.397,308.539 177.397,309.539 179.397,309.539
1V8@1.5A: C485.2 C486.2 C487.2 C488.2 C489.2 C490.2 C553.2 C561.2 C729.2 C730.2 R394.2 U39.13 U39.48 U45.28 U45.30 U50.8 U58.8
2V5@1.5A: C499.2 C500.2 C501.2 C502.2 C503.2 C504.2 C551.2 C782.2 C783.2 C784.2 C785.2 C786.2 C787.2 C788.2 C789.2 R391.2 R392.2 U8.B1 U8.R6 U9.B1 U9.R6 U10.B1 U10.R6 U11.B1 U11.R6 U39.3 U39.9 U49.8 | length 8.4
  L1 w0.2: U8.B1@206.857,328.86 v4(207.785,328.86)
  L1 w0.25: U9.B1@172.476,328.86 v4(172.879,328.457) ; v4(177.133,339.664) U11.R6@177.536,339.26 ; U11.B1@183.936,328.86 v4(184.507,328.86) ; v4(188.593,339.664) U10.R6@188.997,339.26
  L1 w0.254: 199.032,340.739 199.094,340.676 199.094,340.623 U8.R6@200.457,339.26
  L1 w0.3: U10.B1@195.397,328.86 195.841,328.86 196.888,329.908 198.022,329.908 198.044,329.886 v1(198.044,329.87)
  L16 w0.3: v1(198.044,329.87) v1@198.044,329.895
3.3V_LN_1: C55.2 C56.2 C59.2 C60.2 C65.2 C66.2 C71.2 C72.2 C84.2 C85.2 C94.2 C95.2 C569.2 FB2.1 FB3.1 FB4.1 FB5.1 FB6.1 FB7.1 FB33.2
3.3V_PS_Config: C491.2 C492.2 C493.2 C494.2 C495.2 C496.2 C497.2 C498.2 C531.1 C547.2 C612.2 C613.2 C614.2 C615.2 C742.1 C743.2 C790.2 L17.2 R83.2 R84.2 R85.2 R86.2 R97.2 R98.2 R99.2 R106.1 R123.2 R216.1 R319.2 R320.2 R322.2 R323.2 R333.1 R336.1 R337.1 R338.1 R346.1 R347.1 R348.1 R349.2 R350.2 R351.2 R352.2 R353.1 R354.2 R355.1 R356.1 R357.2 R367.2 R368.2 R369.2 R370.2 R371.2 R372.2 R381.2 R382.2 R709.1 R710.2 R715.2 R716.2 R717.2 R718.2 R719.2 R737.2 U1.B22 U1.B27 U1.D18 U1.D23 U1.D28 U1.E21 U1.E26 U1.F19 U1.J18 U1.N20 U1.P18 U39.19 U39.30 U39.41 U43.1 U43.2 U43.7 U43.8 U43.15 U43.16 U44.1 U47.B3 U47.C4 U56.15 U68.3 U76.5 X6.1 X6.4
  other v2: 165.397,305.539 170.397,305.539 175.397,305.539 167.397,306.539 174.397,307.539 166.397,308.539 163.397,309.539 165.397,310.539 166.397,313.539 163.397,314.539 165.397,315.539
3.3V_Stable_1: C149.2 C150.2 C151.2 C152.2 C153.2 C154.2 C155.2 C156.2 C157.2 C158.2 C159.2 C160.2 C161.2 C181.2 C182.2 C183.2 C184.2 C185.2 C186.2 C187.2 C188.2 C189.2 C190.2 C191.2 C192.2 C193.2 C565_U_5V_to_3V33.2 C566_U_5V_to_3V33.2 C567_U_5V_to_3V33.2 R430_U_5V_to_3V33.2 R431_U_5V_to_3V33.2 U12.2 U12.5 U12.8 U12.11 U12.14 U12.17 U12.20 U12.23 U12.26 U12.29 U12.32 U12.35 U59_U_5V_to_3V33.8
3.3V_Stable_2: C166.2 C167.2 C168.2 C169.2 C170.2 C171.2 C172.2 C173.2 C174.2 C175.2 C176.2 C177.2 C178.2 C194.2 C195.2 C196.2 C197.2 C198.2 C199.2 C200.2 C201.2 C202.2 C203.2 C204.2 C205.2 C206.2 C565_U_5V_to_3V32.2 C566_U_5V_to_3V32.2 C567_U_5V_to_3V32.2 R430_U_5V_to_3V32.2 R431_U_5V_to_3V32.2 U13.2 U13.5 U13.8 U13.11 U13.14 U13.17 U13.20 U13.23 U13.26 U13.29 U13.32 U13.35 U59_U_5V_to_3V32.8
3.3V_Stable_3: C111.2 C112.2 C113.2 C114.2 C115.2 C116.2 C117.2 C118.2 C119.2 C120.2 C121.2 C122.2 C123.2 C128.2 C129.2 C130.2 C131.2 C132.2 C133.2 C134.2 C135.2 C136.2 C137.2 C138.2 C139.2 C140.2 C565_U_5V_to_3V31.2 C566_U_5V_to_3V31.2 C567_U_5V_to_3V31.2 R430_U_5V_to_3V31.2 R431_U_5V_to_3V31.2 U14.2 U14.5 U14.8 U14.11 U14.14 U14.17 U14.20 U14.23 U14.26 U14.29 U14.32 U14.35 U59_U_5V_to_3V31.8
3.3Vaux: C332.2 J27.2 J27.4 J27.12 J27.14 J27.16 J27.18 J27.62 J27.64 J27.66 U18.C2 U18.D1 U18.D2 U18.E1 U18.E2 U18.F1 U18.F2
